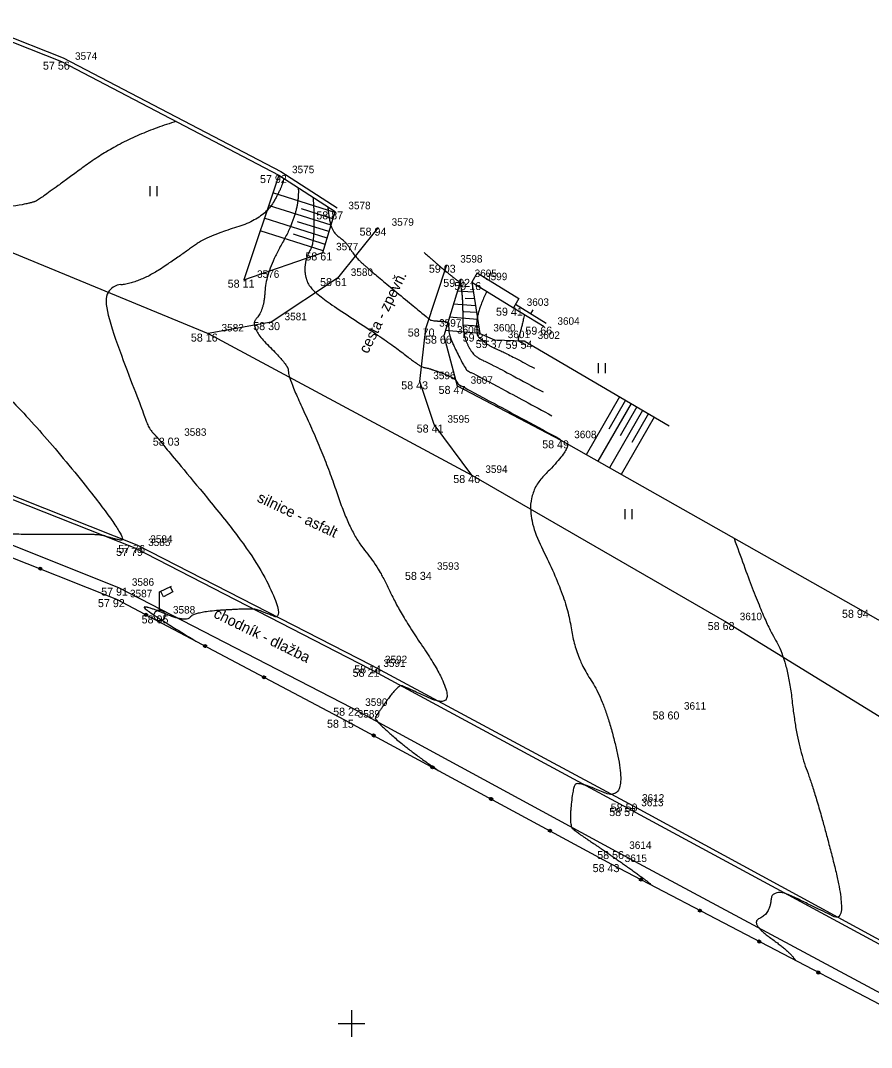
# Model space of a CAD drawing. Extents: x -704017 to -701500, y -1008977 to -1008450.
# Drawn here: x -702012.4 to -701980.53, y -1008850.9 to -1008812.42 of the extents above; entities that cross this region are included whole.
import ezdxf

# ---------------------------------------------------------------- set-up
doc = ezdxf.new("R2010")
doc.units = 0
for name, color, linetype in [('Z_body', 7, 'Continuous'), ('Z_body_cisla', 7, 'Continuous'), ('Z_body_vysky', 7, 'Continuous'), ('Z_cesty', 7, 'Continuous'), ('Z_chodnik', 7, 'Continuous'), ('Z_hekt_sit', 7, 'Continuous'), ('Z_komunikace', 7, 'Continuous'), ('Z_obruby', 7, 'Continuous'), ('Z_oploceni', 7, 'Continuous'), ('Z_popis', 7, 'Continuous'), ('Z_site_znaky_pilire', 7, 'Continuous'), ('Z_site_znaky_VO', 7, 'Continuous'), ('Z_teren_hrany_paty', 7, 'Continuous'), ('Z_vrstevnice_hlavni', 7, 'Continuous'), ('Z_vrstevnice_vedlejsi', 7, 'Continuous'), ('Z_zabradli', 7, 'Continuous')]:
    doc.layers.add(name, color=color, linetype=linetype)

# ---------------------------------------------------------------- blocks, each defined once
blk = doc.blocks.new('POINT_DISPLAY')
blk.add_line((0, 0), (0, 0))
blk = doc.blocks.new('Z210')
blk.add_line((0, 0), (0, 0.17))
blk = doc.blocks.new('Z530')
for p, q in [((-0.05, 0.03), (-0.03, 0.05)), ((-0.05, -0.03), (-0.05, 0.03)), ((-0.03, 0.05), (0.03, 0.05)), ((-0.03, -0.03), (-0.03, 0.03)), ((-0.03, 0.03), (0.03, 0.03)), ((-0.03, -0.03), (0.03, 0.03)), ((0.03, 0.05), (0.05, 0.03)), ((0.03, 0.03), (0.03, -0.03)), ((0.05, 0.03), (0.05, -0.03)), ((-0.03, -0.05), (-0.05, -0.03)), ((0.03, -0.03), (-0.03, -0.03)), ((0.03, -0.05), (-0.03, -0.05)), ((0.05, -0.03), (0.03, -0.05))]:
    blk.add_line(p, q)
blk = doc.blocks.new('Z306')
for p, q in [((-0.13, 0.17), (-0.13, -0.2)), ((0.13, 0.17), (0.13, -0.2))]:
    blk.add_line(p, q)
blk = doc.blocks.new('Z13')
for p, q in [((0, 0.88), (0.45, 1.1)), ((0, 0.2), (0, 0.88)), ((0.15, 0.7), (0.05, 0.9)), ((0.5, 0.88), (0.15, 0.7)), ((0.4, 1.07), (0.5, 0.88)), ((-0.2, 0.05), (-0.15, 0.15)), ((-0.2, -0.05), (-0.2, 0.05)), ((-0.15, 0.15), (-0.05, 0.2)), ((-0.05, 0.2), (0.05, 0.2)), ((0.05, 0.2), (0.15, 0.15)), ((0.15, 0.15), (0.2, 0.05)), ((0.2, 0.05), (0.2, -0.05)), ((-0.15, -0.15), (-0.2, -0.05)), ((-0.05, -0.2), (-0.15, -0.15)), ((0.05, -0.2), (-0.05, -0.2)), ((0.15, -0.15), (0.05, -0.2)), ((0.2, -0.05), (0.15, -0.15))]:
    blk.add_line(p, q)

msp = doc.modelspace()

# ---------------------------------------------------------------- linework, layer by layer
at = {"layer": 'Z_cesty'}
for p, q in [((-701999, -1008820.18), (-702000.53, -1008822.07)), ((-701997.22, -1008823.96), (-701996.43, -1008821.57)), ((-702000.53, -1008822.07), (-702003.01, -1008823.72)), ((-702003.01, -1008823.72), (-702005.37, -1008824.15)), ((-701997.44, -1008825.94), (-701997.22, -1008823.96)), ((-701996.91, -1008827.56), (-701997.44, -1008825.94)), ((-701995.49, -1008829.45), (-701996.91, -1008827.56))]:
    msp.add_line(p, q, dxfattribs=at)
at = {"layer": 'Z_chodnik'}
for p, q in [((-702019.62, -1008829.3), (-702008.73, -1008833.67)), ((-702008.73, -1008833.67), (-701999.99, -1008838.17)), ((-701999.99, -1008838.17), (-701990.1, -1008843.54)), ((-701990.1, -1008843.54), (-701976.94, -1008850.62))]:
    msp.add_line(p, q, dxfattribs=at)
at = {"layer": 'Z_hekt_sit'}
for p, q in [((-702000, -1008849.5), (-702000, -1008850.5)), ((-702000.5, -1008850), (-701999.5, -1008850))]:
    msp.add_line(p, q, dxfattribs=at)
at = {"layer": 'Z_komunikace'}
for p, q in [((-702016.23, -1008819.67), (-702005.37, -1008824.15)), ((-702005.37, -1008824.15), (-701995.49, -1008829.45)), ((-702019.34, -1008827.59), (-702008.04, -1008832.07)), ((-701995.49, -1008829.45), (-701985.96, -1008834.96)), ((-702008.04, -1008832.07), (-701999.25, -1008836.58)), ((-701985.96, -1008834.96), (-701975.47, -1008841.43)), ((-701999.25, -1008836.58), (-701989.62, -1008841.76)), ((-701989.62, -1008841.76), (-701976.08, -1008849.13))]:
    msp.add_line(p, q, dxfattribs=at)
at = {"layer": 'Z_obruby'}
for p, q in [((-702019.38, -1008827.73), (-702008.12, -1008832.18)), ((-702008.12, -1008832.18), (-701999.31, -1008836.71)), ((-701999.31, -1008836.71), (-701989.65, -1008841.93)), ((-701989.65, -1008841.93), (-701976.14, -1008849.24))]:
    msp.add_line(p, q, dxfattribs=at)
at = {"layer": 'Z_oploceni'}
for p, q in [((-702014.34, -1008812.42), (-702010.8, -1008813.82)), ((-702014.39, -1008812.56), (-702010.86, -1008813.96)), ((-702010.86, -1008813.96), (-702002.73, -1008818.21)), ((-702010.8, -1008813.82), (-702002.65, -1008818.08)), ((-702002.73, -1008818.21), (-702000.62, -1008819.57)), ((-702002.65, -1008818.08), (-702000.54, -1008819.44)), ((-701993.94, -1008823.18), (-701992.79, -1008823.89)), ((-701993.86, -1008823.05), (-701992.71, -1008823.76))]:
    msp.add_line(p, q, dxfattribs=at)
at = {"layer": 'Z_site_znaky_pilire'}
for p, q in [((-701995.29, -1008821.88), (-701995.5, -1008822.22)), ((-701995.29, -1008821.88), (-701993.73, -1008822.84)), ((-701995.5, -1008822.22), (-701993.94, -1008823.18)), ((-701993.73, -1008822.84), (-701993.94, -1008823.18))]:
    msp.add_line(p, q, dxfattribs=at)
at = {"layer": 'Z_teren_hrany_paty'}
for p, q in [((-702002.73, -1008818.21), (-702004.04, -1008822.13)), ((-702000.63, -1008819.61), (-702002.95, -1008818.87)), ((-702000.77, -1008820.09), (-702003.11, -1008819.35)), ((-702000.7, -1008819.85), (-702001.87, -1008819.48)), ((-702001.08, -1008821.11), (-702000.62, -1008819.57)), ((-702000.92, -1008820.57), (-702003.27, -1008819.82)), ((-702000.85, -1008820.33), (-702002.02, -1008819.96)), ((-702001.06, -1008821.05), (-702003.43, -1008820.3)), ((-702000.99, -1008820.81), (-702002.17, -1008820.43)), ((-702004.04, -1008822.13), (-702001.08, -1008821.11)), ((-701995.89, -1008822.1), (-701996.55, -1008824.23)), ((-701995.5, -1008822.22), (-701995.19, -1008824.15)), ((-701995.44, -1008822.6), (-701996.03, -1008822.56)), ((-701995.4, -1008822.85), (-701995.75, -1008822.83)), ((-701995.36, -1008823.11), (-701996.18, -1008823.05)), ((-701995.28, -1008823.62), (-701996.34, -1008823.54)), ((-701995.32, -1008823.36), (-701995.79, -1008823.33)), ((-701995.24, -1008823.87), (-701995.82, -1008823.83)), ((-701996.55, -1008824.23), (-701996.04, -1008826.11)), ((-701995.19, -1008824.15), (-701996.49, -1008824.03)), ((-701995.19, -1008824.15), (-701994.65, -1008824.39)), ((-701994.65, -1008824.39), (-701993.53, -1008824.42)), ((-701993.53, -1008824.42), (-701988.1, -1008827.61)), ((-701996.04, -1008826.11), (-701992.16, -1008828.15)), ((-701989.96, -1008826.52), (-701991.21, -1008828.69)), ((-701989.74, -1008826.65), (-701990.37, -1008827.73)), ((-701989.53, -1008826.77), (-701990.77, -1008828.93)), ((-701989.1, -1008827.03), (-701990.34, -1008829.18)), ((-701989.31, -1008826.9), (-701989.94, -1008827.98)), ((-701988.67, -1008827.28), (-701989.9, -1008829.43)), ((-701988.88, -1008827.15), (-701989.5, -1008828.23)), ((-701992.16, -1008828.15), (-701980.93, -1008834.5)), ((-701980.93, -1008834.5), (-701971.48, -1008839.92))]:
    msp.add_line(p, q, dxfattribs=at)
at = {"layer": 'Z_vrstevnice_hlavni'}
for points in [[(-702002.552, -1008818.325), (-702002.539, -1008818.546), (-702003.282, -1008819.861), (-702005.404, -1008820.496), (-702006.295, -1008821.151), (-702007.989, -1008822.283), (-702009.608, -1008822.402), (-702007.784, -1008827.152), (-702007.595, -1008827.713), (-702007.28, -1008828.031), (-702006.911, -1008828.497), (-702003.596, -1008832.488), (-702002.488, -1008834.918), (-702003.384, -1008834.545), (-702003.715, -1008834.445), (-702005.904, -1008834.582), (-702006.193, -1008834.976), (-702007.74, -1008834.339), (-702007.809, -1008834.475), (-702005.833, -1008835.672)], [(-701997.287, -1008821.107), (-701996.723, -1008821.606), (-701996.502, -1008821.787), (-701995.973, -1008822.216), (-701995.927, -1008822.218), (-701995.836, -1008822.863), (-701995.839, -1008824.188), (-701995.504, -1008824.873), (-701995.221, -1008825.097), (-701994.797, -1008825.273), (-701992.825, -1008826.338)]]:
    msp.add_open_spline(points, degree=2, dxfattribs=at)
at = {"layer": 'Z_vrstevnice_vedlejsi'}
for points in [[(-702006.569, -1008816.203), (-702008.504, -1008816.782), (-702011.42, -1008818.925), (-702012.081, -1008819.367), (-702016.23, -1008819.67), (-702014.467, -1008824.909), (-702011.526, -1008827.876), (-702008.28, -1008831.975), (-702009.018, -1008831.813), (-702009.371, -1008831.686), (-702010.12, -1008831.679), (-702013.708, -1008831.672), (-702014.832, -1008831.496), (-702015.028, -1008831.624)], [(-702001.997, -1008818.682), (-702001.941, -1008819.597), (-702003.211, -1008821.844), (-702003.281, -1008823.302), (-702003.853, -1008823.874), (-702002.324, -1008825.378), (-702002.406, -1008825.74), (-702000.999, -1008828.766), (-702000.049, -1008831.62), (-701998.967, -1008832.923), (-701998.177, -1008834.655), (-701996.572, -1008836.994), (-701996.308, -1008838.163), (-701997.973, -1008837.407), (-701998.237, -1008837.29), (-701999.104, -1008838.492), (-701999.117, -1008838.644), (-701997.79, -1008839.82), (-701996.699, -1008840.552)], [(-702001.442, -1008819.04), (-702001.343, -1008820.648), (-702001.731, -1008821.334), (-702001.765, -1008822.036), (-702001.41, -1008822.655), (-701998.642, -1008824.435), (-701997.383, -1008825.427), (-701997.169, -1008825.42), (-701996.121, -1008825.813), (-701996.01, -1008826.04), (-701995.994, -1008826.053), (-701995.97, -1008826.063), (-701992.173, -1008828.114)], [(-702000.887, -1008819.398), (-702000.832, -1008820.281), (-702000.198, -1008820.715), (-701999.881, -1008821.268), (-701999.163, -1008821.903), (-701997.1, -1008823.598), (-701997.012, -1008823.669), (-701996.385, -1008823.698), (-701996.361, -1008823.868), (-701996.362, -1008824.219), (-701995.757, -1008825.457), (-701995.608, -1008825.575), (-701995.383, -1008825.668), (-701992.499, -1008827.226)], [(-701994.938, -1008822.566), (-701995.314, -1008823.378), (-701995.316, -1008824.157), (-701995.251, -1008824.29), (-701994.835, -1008824.619), (-701994.21, -1008824.878), (-701993.152, -1008825.45)], [(-701993.526, -1008823.436), (-701993.656, -1008824.038), (-701993.794, -1008824.413), (-701993.624, -1008824.483), (-701993.478, -1008824.562)], [(-701991.91, -1008828.291), (-701991.834, -1008828.508), (-701993.757, -1008830.452), (-701991.964, -1008833.965), (-701991.608, -1008836.298), (-701990.485, -1008837.934), (-701989.62, -1008841.76), (-701991.528, -1008840.915), (-701991.718, -1008841.178), (-701991.845, -1008842.592), (-701991.588, -1008842.82), (-701990.178, -1008843.766), (-701988.789, -1008844.762), (-701988.763, -1008844.818)], [(-701985.672, -1008831.819), (-701984.606, -1008834.836), (-701983.665, -1008836.375), (-701983.333, -1008839.48), (-701982.545, -1008841.595), (-701981.364, -1008846.254), (-701982.466, -1008845.742), (-701984.246, -1008844.854), (-701984.334, -1008845.894), (-701985.099, -1008846.23), (-701983.499, -1008847.377), (-701983.382, -1008847.634)]]:
    msp.add_open_spline(points, degree=2, dxfattribs=at)
at = {"layer": 'Z_zabradli'}
for p, q in [((-702019.79, -1008829.73), (-702008.8, -1008834.1)), ((-702008.8, -1008834.1), (-702000.27, -1008838.62)), ((-702000.27, -1008838.62), (-701990.27, -1008844.03)), ((-701990.27, -1008844.03), (-701977.14, -1008850.9))]:
    msp.add_line(p, q, dxfattribs=at)

# ---------------------------------------------------------------- block references
at = {"layer": 'Z_body'}
for p in [(-702010.86, -1008813.96), (-702002.73, -1008818.21), (-702000.62, -1008819.57), (-701999, -1008820.18), (-702001.08, -1008821.11), (-701996.43, -1008821.57), (-702000.53, -1008822.07), (-702004.04, -1008822.13), (-701995.89, -1008822.1), (-701995.5, -1008822.22), (-701993.94, -1008823.18), (-702003.01, -1008823.72), (-701997.22, -1008823.96), (-701992.79, -1008823.89), (-702005.37, -1008824.15), (-701996.55, -1008824.23), (-701995.19, -1008824.15), (-701994.65, -1008824.39), (-701993.53, -1008824.42), (-701997.44, -1008825.94), (-701996.04, -1008826.11), (-701996.91, -1008827.56), (-702006.77, -1008828.05), (-701992.16, -1008828.15), (-701995.49, -1008829.45), (-702008.04, -1008832.07), (-702008.12, -1008832.18), (-701997.3, -1008833.08), (-702008.73, -1008833.67), (-702008.8, -1008834.1), (-702007.19, -1008834.71), (-701980.93, -1008834.5), (-701985.96, -1008834.96), (-701999.25, -1008836.58), (-701999.31, -1008836.71), (-701999.99, -1008838.17), (-702000.27, -1008838.62), (-701988.05, -1008838.31), (-701989.65, -1008841.93), (-701989.62, -1008841.76), (-701990.1, -1008843.54), (-701990.27, -1008844.03)]:
    msp.add_blockref('POINT_DISPLAY', p, dxfattribs=at)
at = {"layer": 'Z_oploceni', "rotation": -31.699999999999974}
msp.add_blockref('Z210', (-701993.29, -1008823.41), dxfattribs=at)
at = {"layer": 'Z_popis'}
for p in [(-702007.43, -1008818.8), (-701990.63, -1008825.43), (-701989.63, -1008830.9)]:
    msp.add_blockref('Z306', p, dxfattribs=at)
at = {"layer": 'Z_site_znaky_VO'}
msp.add_blockref('Z13', (-702007.19, -1008834.71), dxfattribs=at)
at = {"layer": 'Z_zabradli'}
for p, rotation in [((-702011.66, -1008832.96), -21.699999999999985), ((-702007.7, -1008834.69), 152.1), ((-702005.49, -1008835.86), 152.1), ((-702003.28, -1008837.03), 152.1), ((-701999.17, -1008839.21), 151.6), ((-701996.97, -1008840.4), 151.6), ((-701994.77, -1008841.59), 151.6), ((-701992.57, -1008842.78), 151.6), ((-701989.16, -1008844.61), 152.4), ((-701986.95, -1008845.77), 152.4), ((-701984.73, -1008846.93), 152.4), ((-701982.52, -1008848.09), 152.4)]:
    msp.add_blockref('Z530', p, dxfattribs=dict(at, rotation=rotation))

# ---------------------------------------------------------------- texts
at = {"layer": 'Z_body_cisla'}
for s, p in [('3574', (-702010.36, -1008813.89)), ('3575', (-702002.23, -1008818.14)), ('3578', (-702000.12, -1008819.49)), ('3579', (-701998.5, -1008820.11)), ('3577', (-702000.58, -1008821.03)), ('3598', (-701995.93, -1008821.49)), ('3576', (-702003.54, -1008822.06)), ('3580', (-702000.03, -1008821.99)), ('3605', (-701995.39, -1008822.03)), ('3599', (-701995, -1008822.15)), ('3603', (-701993.44, -1008823.11)), ('3581', (-702002.51, -1008823.65)), ('3597', (-701996.72, -1008823.89)), ('3604', (-701992.29, -1008823.82)), ('3582', (-702004.87, -1008824.07)), ('3606', (-701996.05, -1008824.15)), ('3600', (-701994.69, -1008824.07)), ('3601', (-701994.15, -1008824.32)), ('3602', (-701993.03, -1008824.35)), ('3596', (-701996.94, -1008825.86)), ('3607', (-701995.54, -1008826.03)), ('3595', (-701996.41, -1008827.49)), ('3583', (-702006.27, -1008827.98)), ('3608', (-701991.66, -1008828.07)), ('3594', (-701994.99, -1008829.37)), ('3585', (-702007.62, -1008832.11)), ('3584', (-702007.54, -1008831.99)), ('3593', (-701996.8, -1008833)), ('3586', (-702008.23, -1008833.6)), ('3587', (-702008.3, -1008834.03)), ('3588', (-702006.69, -1008834.64)), ('3610', (-701985.46, -1008834.89)), ('3592', (-701998.75, -1008836.5)), ('3591', (-701998.81, -1008836.64)), ('3590', (-701999.49, -1008838.1)), ('3611', (-701987.55, -1008838.24)), ('3589', (-701999.77, -1008838.54)), ('3613', (-701989.15, -1008841.86)), ('3612', (-701989.12, -1008841.69)), ('3614', (-701989.6, -1008843.46)), ('3615', (-701989.77, -1008843.95))]:
    msp.add_text(s, height=0.28, dxfattribs=at).set_placement(p)
at = {"layer": 'Z_body_vysky'}
for s, p in [('57 56', (-702011.56, -1008814.26)), ('57 92', (-702003.43, -1008818.51)), ('58 87', (-702001.32, -1008819.87)), ('58 94', (-701999.7, -1008820.48)), ('58 61', (-702001.73, -1008821.41)), ('59 03', (-701997.105, -1008821.87)), ('58 61', (-702001.18, -1008822.37)), ('58 11', (-702004.64, -1008822.43)), ('59 02', (-701996.565, -1008822.4)), ('59 16', (-701996.15, -1008822.52)), ('59 41', (-701994.59, -1008823.48)), ('58 30', (-702003.685, -1008824.02)), ('58 70', (-701997.895, -1008824.26)), ('59 66', (-701993.49, -1008824.19)), ('58 16', (-702006.02, -1008824.45)), ('58 66', (-701997.25, -1008824.53)), ('59 31', (-701995.84, -1008824.45)), ('59 37', (-701995.35, -1008824.69)), ('59 54', (-701994.23, -1008824.72)), ('58 43', (-701998.14, -1008826.24)), ('58 47', (-701996.74, -1008826.41)), ('58 41', (-701997.56, -1008827.86)), ('58 03', (-702007.445, -1008828.35)), ('58 49', (-701992.86, -1008828.45)), ('58 46', (-701996.19, -1008829.75)), ('57 76', (-702008.74, -1008832.37)), ('57 79', (-702008.82, -1008832.48)), ('58 34', (-701998, -1008833.38)), ('57 91', (-702009.38, -1008833.97)), ('57 92', (-702009.5, -1008834.4)), ('58 05', (-702007.865, -1008835.01)), ('58 94', (-701981.63, -1008834.8)), ('58 68', (-701986.66, -1008835.26)), ('58 14', (-701999.9, -1008836.88)), ('58 21', (-701999.96, -1008837.01)), ('58 22', (-702000.69, -1008838.47)), ('58 15', (-702000.92, -1008838.92)), ('58 60', (-701988.725, -1008838.61)), ('58 57', (-701990.35, -1008842.23)), ('58 50', (-701990.295, -1008842.06)), ('58 56', (-701990.8, -1008843.84)), ('58 43', (-701990.97, -1008844.33))]:
    msp.add_text(s, height=0.3, dxfattribs=at).set_placement(p)
at = {"layer": 'Z_popis'}
for s, rotation, p in [('cesta - zpevň.', 63.9, (-701999.39, -1008824.93)), ('silnice - asfalt', 334.8, (-702003.57, -1008830.43)), ('chodník - dlažba', 333.9, (-702005.2, -1008834.77))]:
    msp.add_text(s, height=0.4, rotation=rotation, dxfattribs=at).set_placement(p)

doc.saveas('drawing.dxf')
